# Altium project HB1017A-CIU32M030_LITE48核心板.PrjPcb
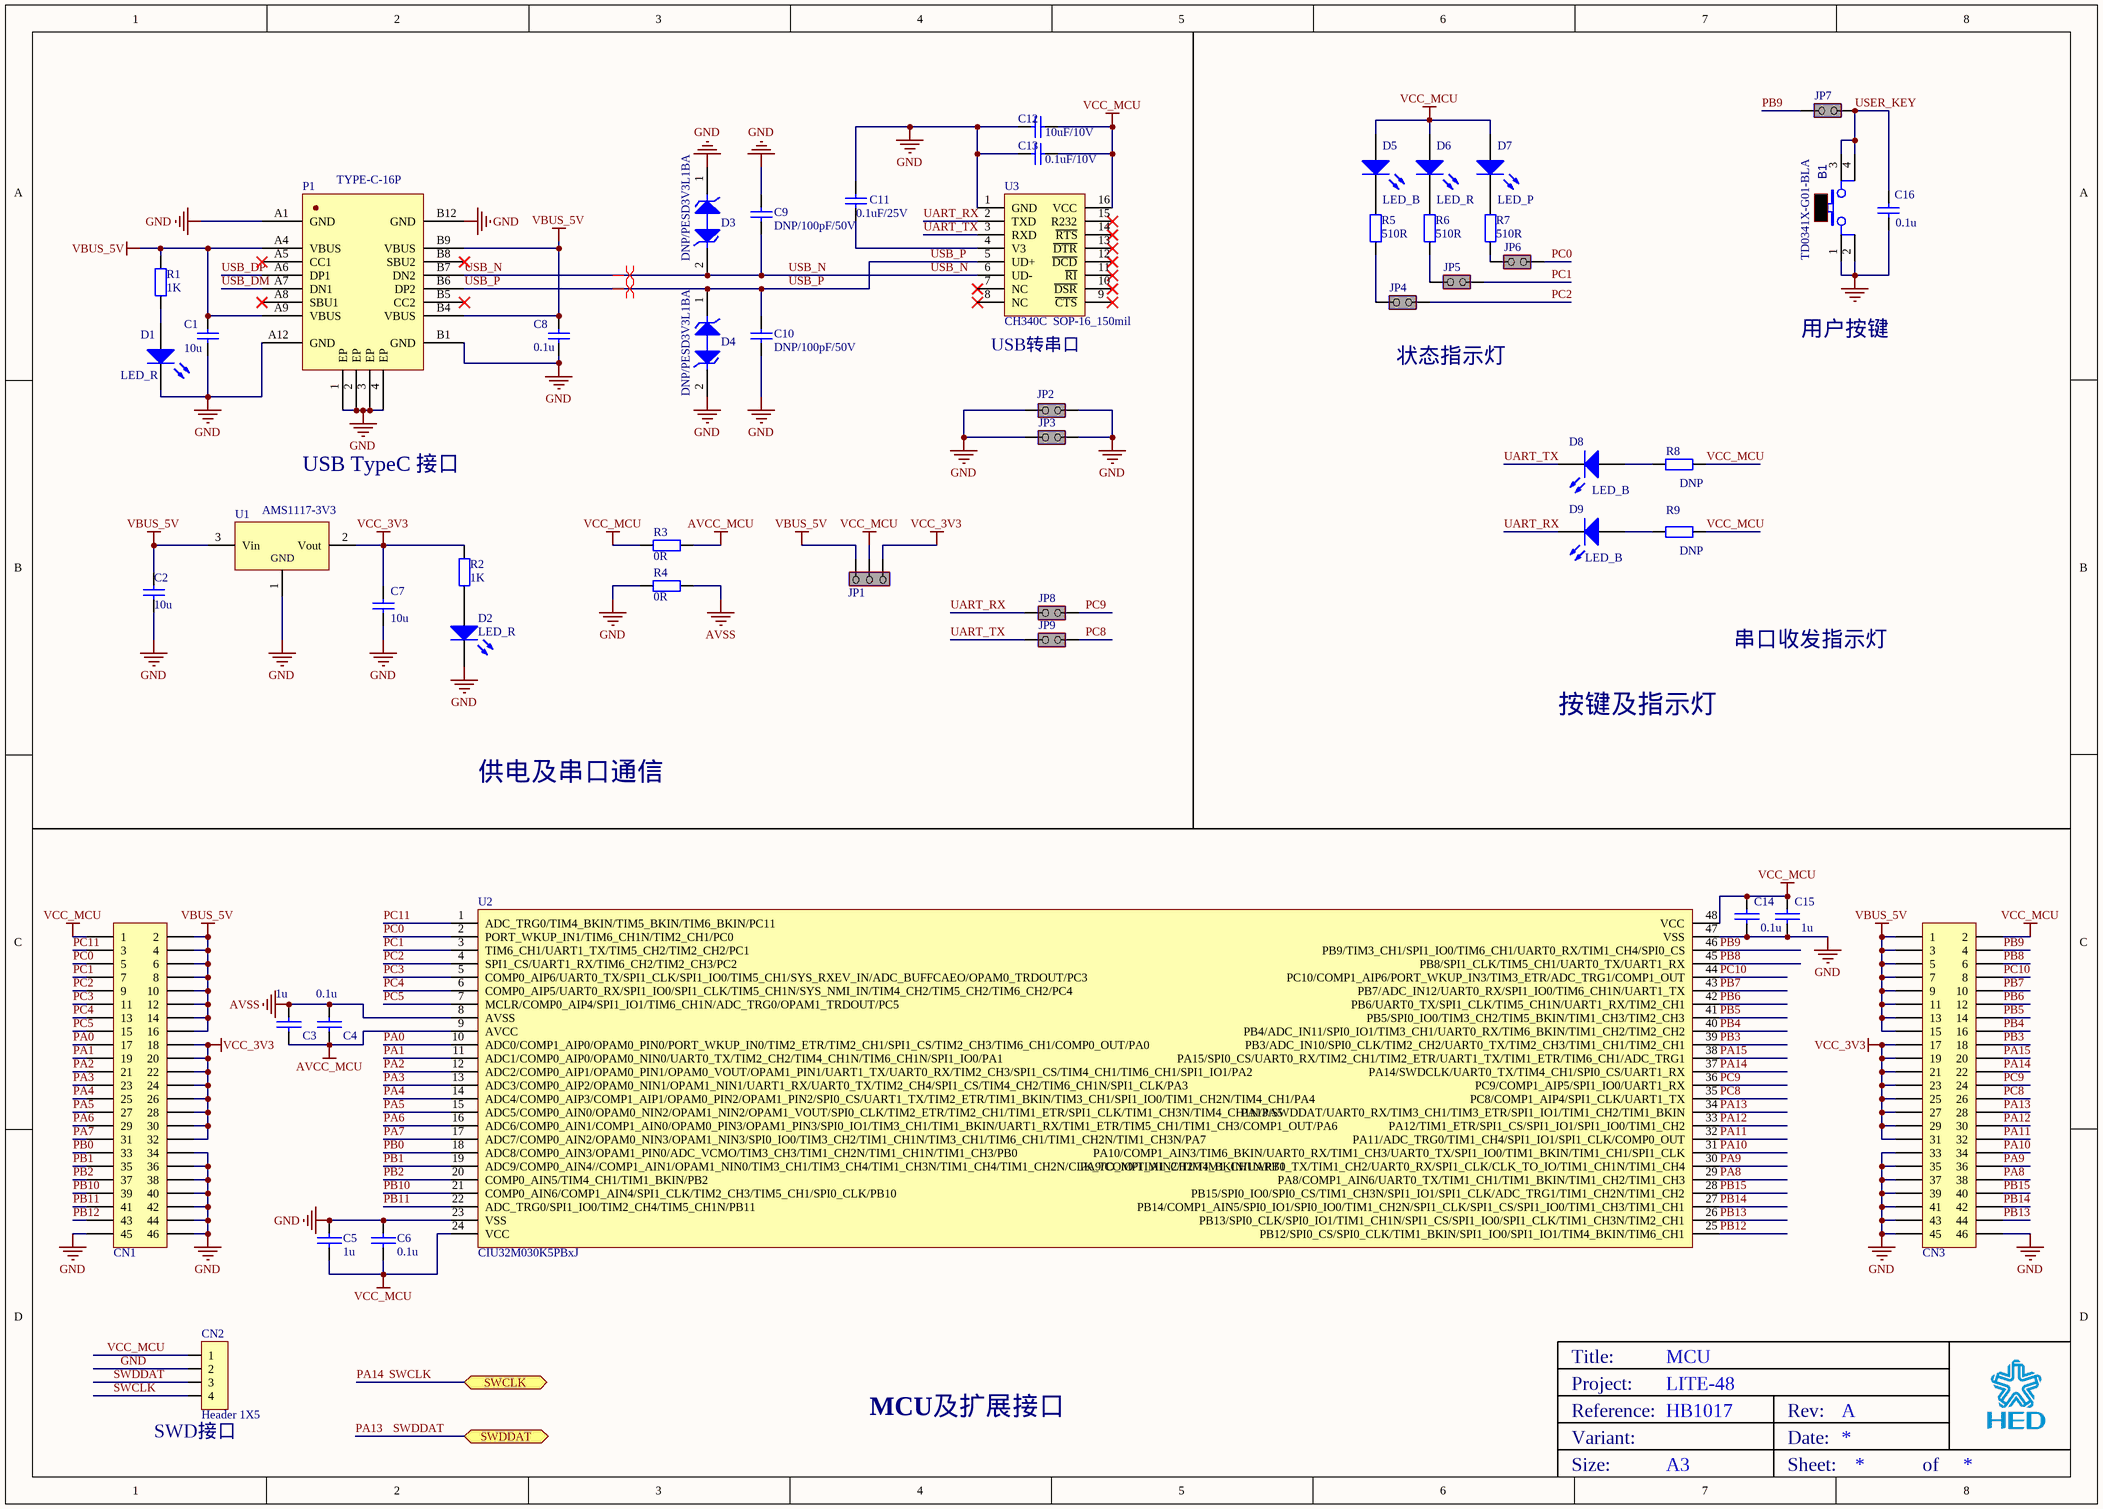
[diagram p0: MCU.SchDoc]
Board_Assembly_Revision: 01; Board_Name: LITE-48; Board_PCB_Revision: A; Board_Reference: HB1017
1 sheet, 51 parts. Net scope: flat (ports and power ports of the same name join across sheets).
Board file: HB1017A_CIU32M030_Lite.PcbDoc

## Sheet MCU.SchDoc: MCU
size A3

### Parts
B1  Manufacturer_Part_Number: TD0341X-G01-BLA  [SWI_WEALTHMETAL_TD-0341_4P_BLACK]  (hidden comment: SW-PUSH-CMS_BLACK)
C1  10u  [0603]
C2  10u  [0603]
C3  1u  [0603C]
C4  0.1u  [0603C]
C5  1u  [0603C]
C6  0.1u  [0603C]
C7  10u  [0603]
C8  0.1u  [0603]
C9  DNP/100pF/50V  [0603C]
C10  DNP/100pF/50V  [0603C]
C11  0.1uF/25V  [0603C]
C12  10uF/10V  [0603C]
C13  0.1uF/10V  [0603C]
C14  0.1u  [0603C]
C15  1u  [0603C]
C16  0.1u  [0603]
CN1  Header 23x2  [HEADER_1X23_2.54]  (value not drawn)
CN2  Header 1X5  [HDR1X4_2.54]
CN3  Header 23x2  [HEADER_1X23_2.54]  (value not drawn)
D1  LED_R  [0603-P]
D2  LED_R  [0603-P]
D3  DNP/PESD3V3L1BA  [SOD323]
D4  DNP/PESD3V3L1BA  [SOD323]
D5  LED_B  [0603-P]
D6  LED_R  [0603-P]
D7  LED_P  [0603-P]
D8  LED_B  [0603-P]
D9  LED_B  [0603-P]
JP1  跳线帽排针  [HDR1X3]  (value not drawn)
JP2  跳线帽排针  [HEADER_1X2_2.54]  (value not drawn)
JP3  跳线帽排针  [HEADER_1X2_2.54]  (value not drawn)
JP4  跳线帽排针  [HEADER_1X2_2.54]  (value not drawn)
JP5  跳线帽排针  [HEADER_1X2_2.54]  (value not drawn)
JP6  跳线帽排针  [HEADER_1X2_2.54]  (value not drawn)
JP7  跳线帽排针  [HEADER_1X2_2.54]  (value not drawn)
JP8  跳线帽排针  [HEADER_1X2_2.54]  (value not drawn)
JP9  跳线帽排针  [HEADER_1X2_2.54]  (value not drawn)
P1  TYPE-C-16P  [HED-KH-TYPE-C-16P]
R1  1K  [0603]
R2  1K  [0603]
R3  0R  [0603]
R4  0R  [0603]
R5  510R  [0603]
R6  510R  [0603]
R7  510R  [0603]
R8  DNP  [0603]
R9  DNP  [0603]
U1  AMS1117-3V3  [SOT223]
U2  CIU32M030K5PBxJ  [LQFP_48N_7X7]
U3  CH340C  SOP-16_150mil  [SO-16]

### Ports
SWCLK, SWDDAT

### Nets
AVCC_MCU: C3.1 C4.1 R3.1 U2.9(AVCC)
AVSS: C3.2 C4.2 R4.1 U2.8(AVSS)
GND: B1.1 B1.2 C1.1 C2.1 C5.2 C6.2 C7.1 C8.1 C9.1 C10.2 C11.1 C12.1 C13.1 C14.1 C15.1 C16.2 CN1.34 CN1.36 CN1.38 CN1.40 CN1.42 CN1.44 CN1.45 CN1.46 CN2.2 CN3.33 CN3.35 CN3.37 CN3.39 CN3.41 CN3.43 CN3.45 CN3.46 D1.2(K) D2.2(K) D3.1 D4.2 JP2.1(COMMON) JP2.2(NO) JP3.1(COMMON) JP3.2(NO) P1.1(EP) P1.2(EP) P1.3(EP) P1.4(EP) P1.A1(GND) P1.A12(GND) P1.B1(GND) P1.B12(GND) R4.2 U1.1(GND) U2.23(VSS) U2.47(VSS) U3.1(GND)
VBUS_5V: C1.2 C2.2 C8.2 CN1.2 CN1.4 CN1.6 CN1.8 CN1.10 CN1.12 CN1.14 CN1.16 CN3.1 CN3.3 CN3.5 CN3.7 CN3.9 CN3.11 CN3.13 CN3.15 JP1.1(COMMON) P1.A4(VBUS) P1.A9(VBUS) P1.B4(VBUS) P1.B9(VBUS) R1.1 U1.3(Vin)
VCC_3V3: C7.2 CN1.18 CN1.20 CN1.22 CN1.24 CN1.26 CN1.28 CN1.30 CN1.32 CN3.17 CN3.19 CN3.21 CN3.23 CN3.25 CN3.27 CN3.29 CN3.31 JP1.3(NO) R2.2 U1.2(Vout)
VCC_MCU: C5.1 C6.1 C12.2 C13.2 C14.2 C15.2 CN1.1 CN2.1 CN3.2 D5.1(A) D6.1(A) D7.1(A) JP1.2(NO) R3.2 R8.1 R9.1 U2.24(VCC) U2.48(VCC) U3.16(VCC)
PA0: CN1.17 U2.10(ADC0/COMP1_AIP0/OPAM0_PIN0/PORT_WKUP_IN0/TIM2_ETR/TIM2_CH1/SPI1_CS/TIM2_CH3/TIM6_CH1/COMP0_OUT/PA0)
PA1: CN1.19 U2.11(ADC1/COMP0_AIP0/OPAM0_NIN0/UART0_TX/TIM2_CH2/TIM4_CH1N/TIM6_CH1N/SPI1_IO0/PA1)
PA2: CN1.21 U2.12(ADC2/COMP0_AIP1/OPAM0_PIN1/OPAM0_VOUT/OPAM1_PIN1/UART1_TX/UART0_RX/TIM2_CH3/SPI1_CS/TIM4_CH1/TIM6_CH1/SPI1_IO1/PA2)
PA3: CN1.23 U2.13(ADC3/COMP0_AIP2/OPAM0_NIN1/OPAM1_NIN1/UART1_RX/UART0_TX/TIM2_CH4/SPI1_CS/TIM4_CH2/TIM6_CH1N/SPI1_CLK/PA3)
PA4: CN1.25 U2.14(ADC4/COMP0_AIP3/COMP1_AIP1/OPAM0_PIN2/OPAM1_PIN2/SPI0_CS/UART1_TX/TIM2_ETR/TIM1_BKIN/TIM3_CH1/SPI1_IO0/TIM1_CH2N/TIM4_CH1/PA4)
PA5: CN1.27 U2.15(ADC5/COMP0_AIN0/OPAM0_NIN2/OPAM1_NIN2/OPAM1_VOUT/SPI0_CLK/TIM2_ETR/TIM2_CH1/TIM1_ETR/SPI1_CLK/TIM1_CH3N/TIM4_CH1N/PA5)
PA6: CN1.29 U2.16(ADC6/COMP0_AIN1/COMP1_AIN0/OPAM0_PIN3/OPAM1_PIN3/SPI0_IO1/TIM3_CH1/TIM1_BKIN/UART1_RX/TIM1_ETR/TIM5_CH1/TIM1_CH3/COMP1_OUT/PA6)
PA7: CN1.31 U2.17(ADC7/COMP0_AIN2/OPAM0_NIN3/OPAM1_NIN3/SPI0_IO0/TIM3_CH2/TIM1_CH1N/TIM3_CH1/TIM6_CH1/TIM1_CH2N/TIM1_CH3N/PA7)
PA8: CN3.38 U2.29(PA8/COMP1_AIN6/UART0_TX/TIM1_CH1/TIM1_BKIN/TIM1_CH2/TIM1_CH3)
PA9: CN3.36 U2.30(PA9/COMP1_AIN2/TIM4_BKIN/UART0_TX/TIM1_CH2/UART0_RX/SPI1_CLK/CLK_TO_IO/TIM1_CH1N/TIM1_CH4)
PA10: CN3.34 U2.31(PA10/COMP1_AIN3/TIM6_BKIN/UART0_RX/TIM1_CH3/UART0_TX/SPI1_IO0/TIM1_BKIN/TIM1_CH1/SPI1_CLK)
PA11: CN3.32 U2.32(PA11/ADC_TRG0/TIM1_CH4/SPI1_IO1/SPI1_CLK/COMP0_OUT)
PA12: CN3.30 U2.33(PA12/TIM1_ETR/SPI1_CS/SPI1_IO1/SPI1_IO0/TIM1_CH2)
PA13: CN2.3 CN3.28 U2.34(PA13/SWDDAT/UART0_RX/TIM3_CH1/TIM3_ETR/SPI1_IO1/TIM1_CH2/TIM1_BKIN) ; port SWDDAT  [also labelled SWDDAT]
PA14: CN2.4 CN3.22 U2.37(PA14/SWDCLK/UART0_TX/TIM4_CH1/SPI0_CS/UART1_RX) ; port SWCLK  [also labelled SWCLK]
PA15: CN3.20 U2.38(PA15/SPI0_CS/UART0_RX/TIM2_CH1/TIM2_ETR/UART1_TX/TIM1_ETR/TIM6_CH1/ADC_TRG1)
PB0: CN1.33 U2.18(ADC8/COMP0_AIN3/OPAM1_PIN0/ADC_VCMO/TIM3_CH3/TIM1_CH2N/TIM1_CH1N/TIM1_CH3/PB0)
PB1: CN1.35 U2.19(ADC9/COMP0_AIN4//COMP1_AIN1/OPAM1_NIN0/TIM3_CH1/TIM3_CH4/TIM1_CH3N/TIM1_CH4/TIM1_CH2N/CLK_TO_IO/TIM1_CH2/TIM1_CH1N/PB1)
PB2: CN1.37 U2.20(COMP0_AIN5/TIM4_CH1/TIM1_BKIN/PB2)
PB3: CN3.18 U2.39(PB3/ADC_IN10/SPI0_CLK/TIM2_CH2/UART0_TX/TIM2_CH3/TIM1_CH1/TIM2_CH1)
PB4: CN3.16 U2.40(PB4/ADC_IN11/SPI0_IO1/TIM3_CH1/UART0_RX/TIM6_BKIN/TIM1_CH2/TIM2_CH2)
PB5: CN3.14 U2.41(PB5/SPI0_IO0/TIM3_CH2/TIM5_BKIN/TIM1_CH3/TIM2_CH3)
PB6: CN3.12 U2.42(PB6/UART0_TX/SPI1_CLK/TIM5_CH1N/UART1_RX/TIM2_CH1)
PB7: CN3.10 U2.43(PB7/ADC_IN12/UART0_RX/SPI1_IO0/TIM6_CH1N/UART1_TX)
PB8: CN3.6 U2.45(PB8/SPI1_CLK/TIM5_CH1/UART0_TX/UART1_RX)
PB9: CN3.4 JP7.1(COMMON) U2.46(PB9/TIM3_CH1/SPI1_IO0/TIM6_CH1/UART0_RX/TIM1_CH4/SPI0_CS)
PB10: CN1.39 U2.21(COMP0_AIN6/COMP1_AIN4/SPI1_CLK/TIM2_CH3/TIM5_CH1/SPI0_CLK/PB10)
PB11: CN1.41 U2.22(ADC_TRG0/SPI1_IO0/TIM2_CH4/TIM5_CH1N/PB11)
PB12: CN1.43 U2.25(PB12/SPI0_CS/SPI0_CLK/TIM1_BKIN/SPI1_IO0/SPI1_IO1/TIM4_BKIN/TIM6_CH1)
PB13: CN3.44 U2.26(PB13/SPI0_CLK/SPI0_IO1/TIM1_CH1N/SPI1_CS/SPI1_IO0/SPI1_CLK/TIM1_CH3N/TIM2_CH1)
PB14: CN3.42 U2.27(PB14/COMP1_AIN5/SPI0_IO1/SPI0_IO0/TIM1_CH2N/SPI1_CLK/SPI1_CS/SPI1_IO0/TIM1_CH3/TIM1_CH1)
PB15: CN3.40 U2.28(PB15/SPI0_IO0/SPI0_CS/TIM1_CH3N/SPI1_IO1/SPI1_CLK/ADC_TRG1/TIM1_CH2N/TIM1_CH2)
PC0: CN1.5 JP6.2(NO) U2.2(PORT_WKUP_IN1/TIM6_CH1N/TIM2_CH1/PC0)
PC1: CN1.7 JP5.2(NO) U2.3(TIM6_CH1/UART1_TX/TIM5_CH2/TIM2_CH2/PC1)
PC2: CN1.9 JP4.2(NO) U2.4(SPI1_CS/UART1_RX/TIM6_CH2/TIM2_CH3/PC2)
PC3: CN1.11 U2.5(COMP0_AIP6/UART0_TX/SPI1_CLK/SPI1_IO0/TIM5_CH1/SYS_RXEV_IN/ADC_BUFFCAEO/OPAM0_TRDOUT/PC3)
PC4: CN1.13 U2.6(COMP0_AIP5/UART0_RX/SPI1_IO0/SPI1_CLK/TIM5_CH1N/SYS_NMI_IN/TIM4_CH2/TIM5_CH2/TIM6_CH2/PC4)
PC5: CN1.15 U2.7(MCLR/COMP0_AIP4/SPI1_IO1/TIM6_CH1N/ADC_TRG0/OPAM1_TRDOUT/PC5)
PC8: CN3.26 JP9.2(NO) U2.35(PC8/COMP1_AIP4/SPI1_CLK/UART1_TX)
PC9: CN3.24 JP8.2(NO) U2.36(PC9/COMP1_AIP5/SPI1_IO0/UART1_RX)
PC10: CN3.8 U2.44(PC10/COMP1_AIP6/PORT_WKUP_IN3/TIM3_ETR/ADC_TRG1/COMP1_OUT)
PC11: CN1.3 U2.1(ADC_TRG0/TIM4_BKIN/TIM5_BKIN/TIM6_BKIN/PC11)
UART_RX: D9.2(K) JP8.1(COMMON) U3.2(TXD)
UART_TX: D8.2(K) JP9.1(COMMON) U3.3(RXD)
USB_DM: P1.A7(DN1)
USB_DP: P1.A6(DP1)
USB_N: C9.2 D3.2 P1.B7(DN2) U3.6(UD-)
USB_P: C10.1 D4.1 P1.B6(DP2) U3.5(UD+)
USER_KEY: B1.3 B1.4 C16.1 JP7.2(NO)
NetC11_2: C11.2 U3.4(V3)
NetD1_1: D1.1(A) R1.2
NetD2_1: D2.1(A) R2.1
NetD5_2: D5.2(K) R5.2
NetD6_2: D6.2(K) R6.1
NetD7_2: D7.2(K) R7.1
NetD8_1: D8.1(A) R8.2
NetD9_1: D9.1(A) R9.2
NetJP4_1: JP4.1(COMMON) R5.1
NetJP5_1: JP5.1(COMMON) R6.2
NetJP6_1: JP6.1(COMMON) R7.2

Not connected (* = marked no-connect by the designer): P1 A5(CC1)* A8(SBU1)* B5(CC2)* B8(SBU2)*; U3 7(NC)* 8(NC)* 9(~{CTS})* 10(~{DSR})* 11(~{RI})* 12(~{DCD})* 13(~{DTR})* 14(~{RTS})* 15(R232)*

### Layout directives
differential pair: USB_N, USB_P

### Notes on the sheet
- USB转串口
- 状态指示灯
- 用户按键
- USB TypeC 接口
- 串口收发指示灯
- 按键及指示灯
- 供电及串口通信
- Project:
- Title:
- (near CN2) SWD接口
- MCU及扩展接口
- Reference:
- Variant:
- Rev:
- Date:
- Size:
- A3
- Sheet:
- of

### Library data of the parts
B1 = MCD-00001: Non-Open Push-Button 0.1A 24V; Part_Type: Misc; Manufacturer: WEALTHMETAL; Value: SW_BLACK; Provided_By: Subcon; Initial_Board_Reference: mb1274
C1 = 0603 4.7uF 10% 16V: 贴片电容
C2 C7 = MCD-00014: 贴片电容; Manufacturer_Part_Number: CC0805KRX5R8BB106; Manufacturer: YAGEO; Provided_By: Subcon; Initial_Board_Reference: mb1274
C3 C5 C15 = CAP: 105贴片电容
C4 = CAP: 104/25V贴片电容
C6 C14 = CAP: 104贴片电容
C8 = 0603 100nF 10% 50V: 贴片电容
C9-C13 = cap 0603: 贴片电容
C16 = MCD-00211: Capacitor, MLCC, 100nF, 16V, X7R, 10%, 0603, T=0,8mm; Manufacturer_Part_Number: CC0603KRX7R7BB104; Manufacturer: YAGEO; Provided_By: Subcon; Initial_Board_Reference: mb1319
CN1 CN3 = Header 23x2: 长排针Header 23x2，2.54mm; Internal_Part_Number: MCD-00213; Manufacturer: SAMTEC; Part_Type: Connector; Manufacturer_Part_Number: TSW-119-09-x-D1; Value: Header 19x2; Provided_By: Subcon; Initial_Board_Reference: mb1319
CN2 = CON4: 排针Header 1X5，2.54mm
D1 = LED3: 红色 SiC LED; sold/unsold: sold
D2 = LED1: 红色 GaAs LED
D3 D4 = TVS
D5 D8 D9 = LED1: 蓝色GaAs LED
D6 = LED1: 红色GaAs LED
D7 = LED1: 粉色GaAs LED
JP1 = Jumper_Header 3x1 Fitted: 跳线帽排针Jumper_Header 1X3 2.54mm
JP2 JP4-JP6 JP8 JP9 = MCD-00683: 跳线帽排针Header, 2x1, 2,54mm,; Part_Type: Connector; Manufacturer_Part_Number: TSW-102-07-x-S; Manufacturer: SAMTEC; Provided_By: Subcon; Initial_Board_Reference: MB1331
JP3 JP7 = MCD-00683: 跳线帽排针Header, 2x1, 2,54mm; Part_Type: Connector; Manufacturer_Part_Number: TSW-102-07-x-S; Manufacturer: SAMTEC; Provided_By: Subcon; Initial_Board_Reference: MB1331
P1 = KH-TYPE-C-16P: TYPE-C USB接口
R1 R2 = Res2: 贴片电阻
R3 R4 = Res: 贴片电阻; Value: 1K
R5-R7 = Res2: 贴片电阻; Value: 1K
R8 R9 = res 0603: 贴片电阻; Value: 1K
U1 = AMS1117: IC REG LDO 5V 0.8A SOT223; Internal_Part_Number: MCD-00088; Manufacturer_Part_Number: LD1117S50TR; Manufacturer: STMICROELECTRONICS; ECCN_US: EAR99; ECCN_EU: NEC; Provided_By: Subcon; Initial_Board_Reference: mb1274
U2 = CIU32M030K5PBxJ: LQFP48
U3 = CH340C: 串口芯片

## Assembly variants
None: all parts fitted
